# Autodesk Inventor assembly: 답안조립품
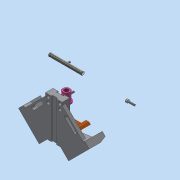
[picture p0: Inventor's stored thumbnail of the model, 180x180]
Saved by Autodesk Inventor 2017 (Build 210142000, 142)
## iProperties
Part Number: 답안조립품
Material: 일반
Document SubType Name: Assembly
Designer: mrc
Author: mrc
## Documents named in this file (11)
- C:\Users\mrc\Desktop\700506V1038\답안조립품.iam
- C:\Users\mrc\Desktop\700506V1038\베이스.ipt
- C:\Users\mrc\Desktop\700506V1038\리드스크류.ipt
- C:\Users\mrc\Desktop\700506V1038\멈춤나사 M4x5.ipt
- C:\Users\mrc\Desktop\700506V1038\멈춤나사 M4x10.ipt
- C:\Users\mrc\Desktop\700506V1038\볼트 M4x16.ipt
- C:\Users\mrc\Desktop\700506V1038\부시.ipt
- C:\Users\mrc\Desktop\700506V1038\서포트.ipt
- C:\Users\mrc\Desktop\700506V1038\조.ipt
- C:\Users\mrc\Desktop\700506V1038\평행 핀 2.5x24.ipt
- C:\Users\mrc\Desktop\700506V1038\핸들.ipt
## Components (1 placed, 1 different names)
1. 핸들:1
